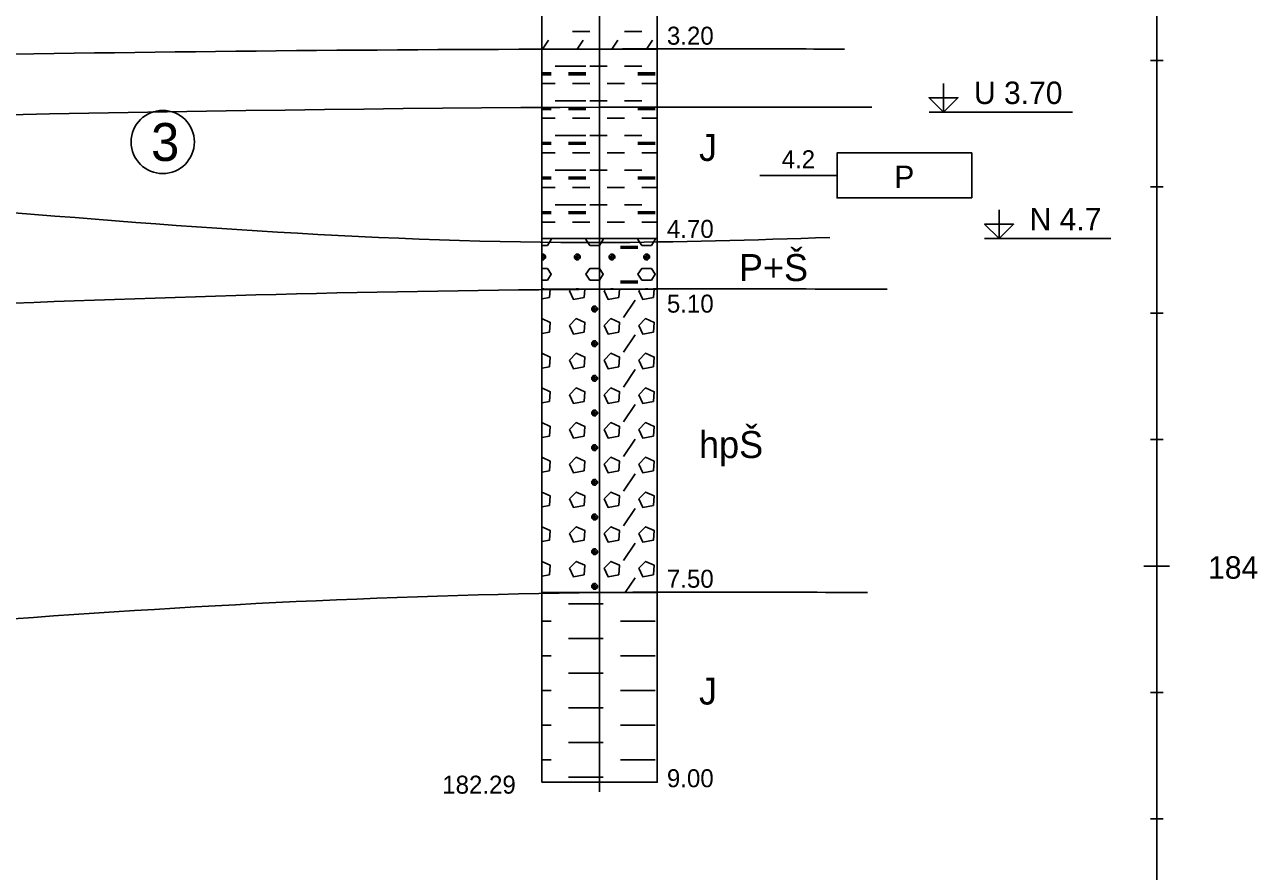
# Model space of a CAD drawing. Extents: x 3042 to 4120, y 576 to 2694.
# Drawn here: x 3483.02 to 3531.8, y 1564.76 to 1598.25 of the extents above; entities that cross this region are included whole.
import ezdxf

# ---------------------------------------------------------------- set-up
doc = ezdxf.new("R2010")
doc.units = 0
for name, color, linetype in [('17', 7, 'Continuous'), ('18', 7, 'Continuous'), ('19', 7, 'Continuous'), ('21', 7, 'Continuous'), ('51', 7, 'Continuous'), ('52', 7, 'Continuous'), ('53', 7, 'Continuous'), ('56', 7, 'Continuous'), ('61', 7, 'Continuous'), ('62', 7, 'Continuous'), ('HPV', 7, 'Continuous'), ('rozhraní', 7, 'Continuous')]:
    doc.layers.add(name, color=color, linetype=linetype)

msp = doc.modelspace()

# ---------------------------------------------------------------- linework, layer by layer
at = {"layer": '18'}
for p, q in [((3505.772, 1568.288), (3505.772, 1613.288)), ((3505.391, 1568.288), (3506.153, 1568.288)), ((3505.772, 1568.669), (3505.772, 1567.907))]:
    msp.add_line(p, q, dxfattribs=at)
at = {"layer": '19'}
for p, q in [((3527.568, 1596.838), (3528.076, 1596.838)), ((3527.568, 1591.838), (3528.076, 1591.838)), ((3527.568, 1586.838), (3528.076, 1586.838)), ((3527.568, 1581.838), (3528.076, 1581.838)), ((3527.314, 1576.838), (3528.33, 1576.838)), ((3527.568, 1571.838), (3528.076, 1571.838)), ((3527.568, 1566.838), (3528.076, 1566.838))]:
    msp.add_line(p, q, dxfattribs=at)
at = {"layer": '21'}
msp.add_line((3527.822, 1551.838), (3527.822, 1621.838), dxfattribs=at)
at = {"layer": '51'}
for p, q in [((3504.702, 1597.979), (3505.388, 1597.979)), ((3506.759, 1597.979), (3507.445, 1597.979)), ((3503.517, 1597.288), (3503.749, 1597.636)), ((3504.889, 1597.288), (3505.121, 1597.636)), ((3506.261, 1597.288), (3506.492, 1597.636)), ((3507.632, 1597.288), (3507.864, 1597.636)), ((3504.016, 1596.607), (3504.702, 1596.607)), ((3504.549, 1596.607), (3505.235, 1596.607)), ((3505.388, 1596.607), (3506.073, 1596.607)), ((3506.759, 1596.607), (3507.445, 1596.607)), ((3503.486, 1596.341), (3503.864, 1596.341)), ((3503.486, 1596.303), (3503.864, 1596.303)), ((3503.486, 1596.264), (3503.864, 1596.264)), ((3504.549, 1596.341), (3505.235, 1596.341)), ((3504.549, 1596.303), (3505.235, 1596.303)), ((3504.549, 1596.264), (3505.235, 1596.264)), ((3507.293, 1596.341), (3507.978, 1596.341)), ((3507.293, 1596.303), (3507.978, 1596.303)), ((3507.293, 1596.264), (3507.978, 1596.264)), ((3503.486, 1595.922), (3504.016, 1595.922)), ((3504.702, 1595.922), (3505.388, 1595.922)), ((3506.073, 1595.922), (3506.759, 1595.922)), ((3507.445, 1595.922), (3508.058, 1595.922)), ((3504.016, 1595.236), (3504.702, 1595.236)), ((3504.549, 1595.236), (3505.235, 1595.236)), ((3505.388, 1595.236), (3506.073, 1595.236)), ((3506.759, 1595.236), (3507.445, 1595.236)), ((3503.486, 1594.969), (3503.864, 1594.969)), ((3503.486, 1594.931), (3503.864, 1594.931)), ((3503.486, 1594.893), (3503.864, 1594.893)), ((3503.486, 1594.55), (3504.016, 1594.55)), ((3504.549, 1594.969), (3505.235, 1594.969)), ((3504.549, 1594.931), (3505.235, 1594.931)), ((3504.549, 1594.893), (3505.235, 1594.893)), ((3504.702, 1594.55), (3505.388, 1594.55)), ((3506.073, 1594.55), (3506.759, 1594.55)), ((3507.293, 1594.969), (3507.978, 1594.969)), ((3507.293, 1594.931), (3507.978, 1594.931)), ((3507.293, 1594.893), (3507.978, 1594.893)), ((3507.445, 1594.55), (3508.058, 1594.55)), ((3503.486, 1593.597), (3503.864, 1593.597)), ((3504.016, 1593.864), (3504.702, 1593.864)), ((3504.549, 1593.864), (3505.235, 1593.864)), ((3504.549, 1593.597), (3505.235, 1593.597)), ((3505.388, 1593.864), (3506.073, 1593.864)), ((3506.759, 1593.864), (3507.445, 1593.864)), ((3507.293, 1593.597), (3507.978, 1593.597)), ((3503.486, 1593.559), (3503.864, 1593.559)), ((3503.486, 1593.521), (3503.864, 1593.521)), ((3503.486, 1593.178), (3504.016, 1593.178)), ((3504.549, 1593.559), (3505.235, 1593.559)), ((3504.549, 1593.521), (3505.235, 1593.521)), ((3504.702, 1593.178), (3505.388, 1593.178)), ((3506.073, 1593.178), (3506.759, 1593.178)), ((3507.293, 1593.559), (3507.978, 1593.559)), ((3507.293, 1593.521), (3507.978, 1593.521)), ((3507.445, 1593.178), (3508.058, 1593.178)), ((3503.486, 1592.226), (3503.864, 1592.226)), ((3503.486, 1592.188), (3503.864, 1592.188)), ((3503.486, 1592.15), (3503.864, 1592.15)), ((3504.016, 1592.493), (3504.702, 1592.493)), ((3504.549, 1592.493), (3505.235, 1592.493)), ((3504.549, 1592.226), (3505.235, 1592.226)), ((3504.549, 1592.188), (3505.235, 1592.188)), ((3504.549, 1592.15), (3505.235, 1592.15)), ((3505.388, 1592.493), (3506.073, 1592.493)), ((3506.759, 1592.493), (3507.445, 1592.493)), ((3507.293, 1592.226), (3507.978, 1592.226)), ((3507.293, 1592.188), (3507.978, 1592.188)), ((3507.293, 1592.15), (3507.978, 1592.15)), ((3503.486, 1591.807), (3504.016, 1591.807)), ((3504.702, 1591.807), (3505.388, 1591.807)), ((3506.073, 1591.807), (3506.759, 1591.807)), ((3507.445, 1591.807), (3508.058, 1591.807)), ((3503.486, 1590.854), (3503.864, 1590.854)), ((3503.486, 1590.816), (3503.864, 1590.816)), ((3503.486, 1590.778), (3503.864, 1590.778)), ((3504.016, 1591.121), (3504.702, 1591.121)), ((3504.549, 1591.121), (3505.235, 1591.121)), ((3504.549, 1590.854), (3505.235, 1590.854)), ((3504.549, 1590.816), (3505.235, 1590.816)), ((3504.549, 1590.778), (3505.235, 1590.778)), ((3505.388, 1591.121), (3506.073, 1591.121)), ((3506.759, 1591.121), (3507.445, 1591.121)), ((3507.293, 1590.854), (3507.978, 1590.854)), ((3507.293, 1590.816), (3507.978, 1590.816)), ((3507.293, 1590.778), (3507.978, 1590.778)), ((3503.486, 1590.435), (3504.016, 1590.435)), ((3504.702, 1590.435), (3505.388, 1590.435)), ((3506.073, 1590.435), (3506.759, 1590.435)), ((3507.445, 1590.435), (3508.058, 1590.435)), ((3506.607, 1589.483), (3507.293, 1589.483)), ((3506.607, 1589.445), (3507.293, 1589.445)), ((3506.607, 1589.406), (3507.293, 1589.406)), ((3503.483, 1589.178), (3503.483, 1589.178)), ((3503.486, 1589.105), (3503.559, 1589.178)), ((3503.521, 1588.949), (3503.521, 1589.178)), ((3504.892, 1588.949), (3504.892, 1589.178)), ((3506.264, 1588.949), (3506.264, 1589.178)), ((3507.635, 1588.949), (3507.635, 1589.178)), ((3503.483, 1587.806), (3503.483, 1587.806)), ((3503.521, 1587.788), (3503.521, 1587.806)), ((3503.541, 1587.788), (3503.559, 1587.806)), ((3504.646, 1587.788), (3504.587, 1587.73)), ((3504.854, 1587.806), (3504.836, 1587.788)), ((3504.892, 1587.788), (3504.892, 1587.806)), ((3504.913, 1587.788), (3504.93, 1587.806)), ((3506.017, 1587.788), (3505.959, 1587.73)), ((3506.226, 1587.806), (3506.208, 1587.788)), ((3506.264, 1587.788), (3506.264, 1587.806)), ((3506.284, 1587.788), (3506.302, 1587.806)), ((3506.607, 1588.111), (3507.293, 1588.111)), ((3506.607, 1588.073), (3507.293, 1588.073)), ((3506.607, 1588.035), (3507.293, 1588.035)), ((3507.389, 1587.788), (3507.331, 1587.73)), ((3507.597, 1587.806), (3507.58, 1587.788)), ((3507.635, 1587.788), (3507.635, 1587.806)), ((3507.656, 1587.788), (3507.674, 1587.806)), ((3506.721, 1586.663), (3507.178, 1587.349)), ((3505.578, 1586.892), (3505.578, 1587.12)), ((3506.721, 1585.292), (3507.178, 1585.977)), ((3505.578, 1585.52), (3505.578, 1585.749)), ((3505.578, 1584.149), (3505.578, 1584.377)), ((3506.721, 1583.92), (3507.178, 1584.606)), ((3505.578, 1582.777), (3505.578, 1583.006)), ((3506.721, 1582.548), (3507.178, 1583.234)), ((3505.578, 1581.405), (3505.578, 1581.634)), ((3506.721, 1581.177), (3507.178, 1581.863)), ((3506.721, 1579.805), (3507.178, 1580.491)), ((3505.578, 1580.034), (3505.578, 1580.262)), ((3506.721, 1578.434), (3507.178, 1579.119)), ((3505.578, 1578.662), (3505.578, 1578.891)), ((3505.578, 1577.291), (3505.578, 1577.519)), ((3506.721, 1577.062), (3507.178, 1577.748)), ((3505.578, 1575.919), (3505.578, 1576.148)), ((3506.786, 1575.788), (3507.178, 1576.376)), ((3504.549, 1575.348), (3505.235, 1575.348)), ((3505.235, 1575.348), (3505.921, 1575.348)), ((3503.486, 1574.662), (3503.864, 1574.662)), ((3506.607, 1574.662), (3507.293, 1574.662)), ((3507.293, 1574.662), (3507.978, 1574.662)), ((3504.549, 1573.976), (3505.235, 1573.976)), ((3505.235, 1573.976), (3505.921, 1573.976)), ((3503.486, 1573.29), (3503.864, 1573.29)), ((3506.607, 1573.29), (3507.293, 1573.29)), ((3507.293, 1573.29), (3507.978, 1573.29)), ((3504.549, 1572.604), (3505.235, 1572.604)), ((3505.235, 1572.604), (3505.921, 1572.604)), ((3503.486, 1571.919), (3503.864, 1571.919)), ((3506.607, 1571.919), (3507.293, 1571.919)), ((3507.293, 1571.919), (3507.978, 1571.919)), ((3504.549, 1571.233), (3505.235, 1571.233)), ((3505.235, 1571.233), (3505.921, 1571.233)), ((3503.486, 1570.547), (3503.864, 1570.547)), ((3506.607, 1570.547), (3507.293, 1570.547)), ((3507.293, 1570.547), (3507.978, 1570.547)), ((3504.549, 1569.861), (3505.235, 1569.861)), ((3505.235, 1569.861), (3505.921, 1569.861)), ((3503.486, 1569.175), (3503.864, 1569.175)), ((3506.607, 1569.175), (3507.293, 1569.175)), ((3507.293, 1569.175), (3507.978, 1569.175)), ((3504.549, 1568.49), (3505.235, 1568.49)), ((3505.235, 1568.49), (3505.921, 1568.49))]:
    msp.add_line(p, q, dxfattribs=at)
for points in [[(3503.486, 1597.288), (3508.058, 1597.288), (3508.058, 1605.288), (3503.486, 1605.288)], [(3503.486, 1589.788), (3508.058, 1589.788), (3508.058, 1597.288), (3503.486, 1597.288)], [(3503.486, 1587.788), (3508.058, 1587.788), (3508.058, 1589.788), (3503.486, 1589.788)], [(3503.486, 1575.788), (3508.058, 1575.788), (3508.058, 1587.788), (3503.486, 1587.788)], [(3503.486, 1568.288), (3508.058, 1568.288), (3508.058, 1575.788), (3503.486, 1575.788)]]:
    msp.add_lwpolyline(points, close=True, dxfattribs=at)
for points in [[(3503.486, 1589.521), (3503.711, 1589.521), (3503.864, 1589.749), (3503.837, 1589.788)], [(3505.261, 1589.788), (3505.235, 1589.749), (3505.388, 1589.521)], [(3505.388, 1589.521), (3505.769, 1589.521), (3505.921, 1589.749), (3505.895, 1589.788)], [(3507.319, 1589.788), (3507.293, 1589.749), (3507.445, 1589.521)], [(3507.445, 1589.521), (3507.826, 1589.521), (3507.978, 1589.749), (3507.952, 1589.788)], [(3503.483, 1588.949), (3503.483, 1588.949), (3503.559, 1588.949), (3503.635, 1589.025), (3503.635, 1589.102), (3503.559, 1589.178), (3503.483, 1589.178), (3503.635, 1589.025), (3503.486, 1589.025)], [(3504.854, 1589.178), (3504.778, 1589.102), (3504.778, 1589.025), (3504.854, 1588.949), (3504.93, 1588.949), (3505.007, 1589.025), (3505.007, 1589.102), (3504.93, 1589.178), (3504.854, 1589.178), (3505.007, 1589.025), (3504.778, 1589.025), (3504.93, 1589.178)], [(3506.226, 1589.178), (3506.15, 1589.102), (3506.15, 1589.025), (3506.226, 1588.949), (3506.302, 1588.949), (3506.378, 1589.025), (3506.378, 1589.102), (3506.302, 1589.178), (3506.226, 1589.178), (3506.378, 1589.025), (3506.15, 1589.025), (3506.302, 1589.178)], [(3507.597, 1589.178), (3507.521, 1589.102), (3507.521, 1589.025), (3507.597, 1588.949), (3507.674, 1588.949), (3507.75, 1589.025), (3507.75, 1589.102), (3507.674, 1589.178), (3507.597, 1589.178), (3507.75, 1589.025), (3507.521, 1589.025), (3507.674, 1589.178)], [(3503.486, 1588.149), (3503.711, 1588.149), (3503.864, 1588.378), (3503.711, 1588.606), (3503.486, 1588.606)], [(3505.388, 1588.149), (3505.769, 1588.149), (3505.921, 1588.378), (3505.769, 1588.606), (3505.388, 1588.606), (3505.235, 1588.378), (3505.388, 1588.149)], [(3507.445, 1588.149), (3507.826, 1588.149), (3507.978, 1588.378), (3507.826, 1588.606), (3507.445, 1588.606), (3507.293, 1588.378), (3507.445, 1588.149)], [(3503.577, 1587.788), (3503.559, 1587.806), (3503.483, 1587.806), (3503.5, 1587.788)], [(3503.486, 1587.408), (3503.787, 1587.463), (3503.82, 1587.788)], [(3504.587, 1587.73), (3504.74, 1587.387), (3505.159, 1587.463), (3505.191, 1587.788)], [(3504.948, 1587.788), (3504.93, 1587.806), (3504.854, 1587.806), (3504.872, 1587.788)], [(3505.959, 1587.73), (3506.111, 1587.387), (3506.531, 1587.463), (3506.563, 1587.788)], [(3506.32, 1587.788), (3506.302, 1587.806), (3506.226, 1587.806), (3506.244, 1587.788)], [(3507.331, 1587.73), (3507.483, 1587.387), (3507.902, 1587.463), (3507.935, 1587.788)], [(3507.691, 1587.788), (3507.674, 1587.806), (3507.597, 1587.806), (3507.615, 1587.788)], [(3505.54, 1587.12), (3505.464, 1587.044), (3505.464, 1586.968), (3505.54, 1586.892), (3505.616, 1586.892), (3505.692, 1586.968), (3505.692, 1587.044), (3505.616, 1587.12), (3505.54, 1587.12), (3505.692, 1586.968), (3505.464, 1586.968), (3505.616, 1587.12)], [(3503.486, 1586.037), (3503.787, 1586.092), (3503.825, 1586.473), (3503.483, 1586.625), (3503.483, 1586.625)], [(3504.587, 1586.358), (3504.74, 1586.016), (3505.159, 1586.092), (3505.197, 1586.473), (3504.854, 1586.625), (3504.587, 1586.358)], [(3505.959, 1586.358), (3506.111, 1586.016), (3506.531, 1586.092), (3506.569, 1586.473), (3506.226, 1586.625), (3505.959, 1586.358)], [(3507.331, 1586.358), (3507.483, 1586.016), (3507.902, 1586.092), (3507.94, 1586.473), (3507.597, 1586.625), (3507.331, 1586.358)], [(3505.54, 1585.749), (3505.464, 1585.673), (3505.464, 1585.596), (3505.54, 1585.52), (3505.616, 1585.52), (3505.692, 1585.596), (3505.692, 1585.673), (3505.616, 1585.749), (3505.54, 1585.749), (3505.692, 1585.596), (3505.464, 1585.596), (3505.616, 1585.749)], [(3503.486, 1584.665), (3503.787, 1584.72), (3503.825, 1585.101), (3503.483, 1585.254), (3503.483, 1585.254)], [(3504.587, 1584.987), (3504.74, 1584.644), (3505.159, 1584.72), (3505.197, 1585.101), (3504.854, 1585.254), (3504.587, 1584.987)], [(3505.959, 1584.987), (3506.111, 1584.644), (3506.531, 1584.72), (3506.569, 1585.101), (3506.226, 1585.254), (3505.959, 1584.987)], [(3507.331, 1584.987), (3507.483, 1584.644), (3507.902, 1584.72), (3507.94, 1585.101), (3507.597, 1585.254), (3507.331, 1584.987)], [(3505.54, 1584.377), (3505.464, 1584.301), (3505.464, 1584.225), (3505.54, 1584.149), (3505.616, 1584.149), (3505.692, 1584.225), (3505.692, 1584.301), (3505.616, 1584.377), (3505.54, 1584.377), (3505.692, 1584.225), (3505.464, 1584.225), (3505.616, 1584.377)], [(3503.486, 1583.294), (3503.787, 1583.349), (3503.825, 1583.73), (3503.483, 1583.882), (3503.483, 1583.882)], [(3504.587, 1583.615), (3504.74, 1583.272), (3505.159, 1583.349), (3505.197, 1583.73), (3504.854, 1583.882), (3504.587, 1583.615)], [(3505.959, 1583.615), (3506.111, 1583.272), (3506.531, 1583.349), (3506.569, 1583.73), (3506.226, 1583.882), (3505.959, 1583.615)], [(3507.331, 1583.615), (3507.483, 1583.272), (3507.902, 1583.349), (3507.94, 1583.73), (3507.597, 1583.882), (3507.331, 1583.615)], [(3505.54, 1583.006), (3505.464, 1582.929), (3505.464, 1582.853), (3505.54, 1582.777), (3505.616, 1582.777), (3505.692, 1582.853), (3505.692, 1582.929), (3505.616, 1583.006), (3505.54, 1583.006), (3505.692, 1582.853), (3505.464, 1582.853), (3505.616, 1583.006)], [(3503.486, 1581.922), (3503.787, 1581.977), (3503.825, 1582.358), (3503.483, 1582.51), (3503.483, 1582.51)], [(3504.587, 1582.244), (3504.74, 1581.901), (3505.159, 1581.977), (3505.197, 1582.358), (3504.854, 1582.51), (3504.587, 1582.244)], [(3505.959, 1582.244), (3506.111, 1581.901), (3506.531, 1581.977), (3506.569, 1582.358), (3506.226, 1582.51), (3505.959, 1582.244)], [(3507.331, 1582.244), (3507.483, 1581.901), (3507.902, 1581.977), (3507.94, 1582.358), (3507.597, 1582.51), (3507.331, 1582.244)], [(3505.54, 1581.634), (3505.464, 1581.558), (3505.464, 1581.482), (3505.54, 1581.405), (3505.616, 1581.405), (3505.692, 1581.482), (3505.692, 1581.558), (3505.616, 1581.634), (3505.54, 1581.634), (3505.692, 1581.482), (3505.464, 1581.482), (3505.616, 1581.634)], [(3503.486, 1580.55), (3503.787, 1580.605), (3503.825, 1580.986), (3503.483, 1581.139), (3503.483, 1581.139)], [(3504.587, 1580.872), (3504.74, 1580.529), (3505.159, 1580.605), (3505.197, 1580.986), (3504.854, 1581.139), (3504.587, 1580.872)], [(3505.959, 1580.872), (3506.111, 1580.529), (3506.531, 1580.605), (3506.569, 1580.986), (3506.226, 1581.139), (3505.959, 1580.872)], [(3507.331, 1580.872), (3507.483, 1580.529), (3507.902, 1580.605), (3507.94, 1580.986), (3507.597, 1581.139), (3507.331, 1580.872)], [(3505.54, 1580.262), (3505.464, 1580.186), (3505.464, 1580.11), (3505.54, 1580.034), (3505.616, 1580.034), (3505.692, 1580.11), (3505.692, 1580.186), (3505.616, 1580.262), (3505.54, 1580.262), (3505.692, 1580.11), (3505.464, 1580.11), (3505.616, 1580.262)], [(3503.486, 1579.179), (3503.787, 1579.234), (3503.825, 1579.615), (3503.483, 1579.767), (3503.483, 1579.767)], [(3504.587, 1579.5), (3504.74, 1579.158), (3505.159, 1579.234), (3505.197, 1579.615), (3504.854, 1579.767), (3504.587, 1579.5)], [(3505.959, 1579.5), (3506.111, 1579.158), (3506.531, 1579.234), (3506.569, 1579.615), (3506.226, 1579.767), (3505.959, 1579.5)], [(3507.331, 1579.5), (3507.483, 1579.158), (3507.902, 1579.234), (3507.94, 1579.615), (3507.597, 1579.767), (3507.331, 1579.5)], [(3505.54, 1578.891), (3505.464, 1578.815), (3505.464, 1578.738), (3505.54, 1578.662), (3505.616, 1578.662), (3505.692, 1578.738), (3505.692, 1578.815), (3505.616, 1578.891), (3505.54, 1578.891), (3505.692, 1578.738), (3505.464, 1578.738), (3505.616, 1578.891)], [(3503.486, 1577.807), (3503.787, 1577.862), (3503.825, 1578.243), (3503.483, 1578.396), (3503.483, 1578.396)], [(3504.587, 1578.129), (3504.74, 1577.786), (3505.159, 1577.862), (3505.197, 1578.243), (3504.854, 1578.396), (3504.587, 1578.129)], [(3505.959, 1578.129), (3506.111, 1577.786), (3506.531, 1577.862), (3506.569, 1578.243), (3506.226, 1578.396), (3505.959, 1578.129)], [(3507.331, 1578.129), (3507.483, 1577.786), (3507.902, 1577.862), (3507.94, 1578.243), (3507.597, 1578.396), (3507.331, 1578.129)], [(3505.54, 1577.519), (3505.464, 1577.443), (3505.464, 1577.367), (3505.54, 1577.291), (3505.616, 1577.291), (3505.692, 1577.367), (3505.692, 1577.443), (3505.616, 1577.519), (3505.54, 1577.519), (3505.692, 1577.367), (3505.464, 1577.367), (3505.616, 1577.519)], [(3503.486, 1576.436), (3503.787, 1576.491), (3503.825, 1576.872), (3503.483, 1577.024), (3503.483, 1577.024)], [(3504.587, 1576.757), (3504.74, 1576.414), (3505.159, 1576.491), (3505.197, 1576.872), (3504.854, 1577.024), (3504.587, 1576.757)], [(3505.959, 1576.757), (3506.111, 1576.414), (3506.531, 1576.491), (3506.569, 1576.872), (3506.226, 1577.024), (3505.959, 1576.757)], [(3507.331, 1576.757), (3507.483, 1576.414), (3507.902, 1576.491), (3507.94, 1576.872), (3507.597, 1577.024), (3507.331, 1576.757)], [(3505.54, 1576.148), (3505.464, 1576.071), (3505.464, 1575.995), (3505.54, 1575.919), (3505.616, 1575.919), (3505.692, 1575.995), (3505.692, 1576.071), (3505.616, 1576.148), (3505.54, 1576.148), (3505.692, 1575.995), (3505.464, 1575.995), (3505.616, 1576.148)]]:
    msp.add_lwpolyline(points, dxfattribs=at)
at = {"layer": '53'}
for p, q in [((3503.486, 1613.288), (3503.486, 1568.288)), ((3508.058, 1613.288), (3508.058, 1568.288)), ((3503.486, 1597.288), (3508.058, 1597.288)), ((3503.486, 1589.788), (3508.058, 1589.788)), ((3503.486, 1587.788), (3508.058, 1587.788)), ((3503.486, 1575.788), (3508.058, 1575.788)), ((3503.486, 1568.288), (3508.058, 1568.288))]:
    msp.add_line(p, q, dxfattribs=at)
at = {"layer": '56'}
for p, q in [((3505.772, 1597.669), (3505.772, 1596.907)), ((3505.391, 1597.288), (3506.153, 1597.288)), ((3505.772, 1590.169), (3505.772, 1589.407)), ((3505.391, 1589.788), (3506.153, 1589.788)), ((3505.391, 1587.788), (3506.153, 1587.788)), ((3505.772, 1588.169), (3505.772, 1587.407)), ((3505.772, 1576.169), (3505.772, 1575.407)), ((3505.391, 1575.788), (3506.153, 1575.788)), ((3505.391, 1568.288), (3506.153, 1568.288)), ((3505.772, 1568.669), (3505.772, 1567.907))]:
    msp.add_line(p, q, dxfattribs=at)
at = {"layer": '61'}
for p, q in [((3518.811, 1594.788), (3524.484, 1594.788)), ((3521.012, 1589.788), (3526.007, 1589.788))]:
    msp.add_line(p, q, dxfattribs=at)
for points in [[(3519.383, 1595.931), (3519.383, 1594.788), (3518.811, 1595.36), (3519.954, 1595.36), (3519.383, 1594.788)], [(3521.583, 1590.931), (3521.583, 1589.788), (3521.012, 1590.36), (3522.155, 1590.36), (3521.583, 1589.788)]]:
    msp.add_lwpolyline(points, dxfattribs=at)
at = {"layer": '62'}
msp.add_line((3512.122, 1592.288), (3515.17, 1592.288), dxfattribs=at)
msp.add_lwpolyline([(3520.504, 1591.399), (3515.17, 1591.399), (3515.17, 1593.177), (3520.504, 1593.177), (3520.504, 1591.399)], dxfattribs=at)
at = {"layer": 'HPV'}
msp.add_spline([(3258.558, 1595.438), (3265.132, 1595.438), (3304.222, 1591.874), (3343.272, 1592.467), (3406.282, 1592.961), (3505.772, 1594.985), (3516.554, 1594.985)], degree=3, dxfattribs=at)
at = {"layer": 'rozhraní'}
msp.add_circle((3488.489, 1593.611), 1.25, dxfattribs=at)
for points in [[(3343.149, 1592.908), (3343.272, 1592.888), (3351.552, 1592.438), (3359.888, 1593.128), (3368.248, 1594.122), (3372.427, 1594.472), (3376.599, 1594.586), (3384.02, 1594.321), (3391.441, 1593.85), (3398.862, 1593.447), (3406.282, 1593.388), (3418.367, 1594.021), (3430.442, 1595.004), (3442.519, 1595.967), (3454.612, 1596.538), (3467.4, 1596.805), (3480.19, 1597.046), (3505.772, 1597.288), (3515.471, 1597.288)], [(3514.887, 1589.833), (3505.845, 1589.635), (3454.612, 1592.538), (3406.282, 1588.388), (3376.599, 1586.586), (3364.06, 1589.145), (3356.751, 1592.851)], [(3388.049, 1585.144), (3406.282, 1583.388), (3454.612, 1585.538), (3505.772, 1587.788), (3517.156, 1587.788)], [(3259.44, 1578.878), (3265.132, 1578.438), (3304.222, 1572.038), (3343.272, 1565.888), (3376.602, 1571.588), (3406.282, 1569.388), (3454.612, 1572.038), (3505.772, 1575.788), (3516.375, 1575.788)]]:
    msp.add_spline(points, degree=3, dxfattribs=at)

# ---------------------------------------------------------------- texts
at = {"layer": '17'}
msp.add_text('182.29', height=0.7112, dxfattribs=at).set_placement((3499.549, 1567.836))
at = {"layer": '19'}
msp.add_text('184', height=0.889, dxfattribs=at).set_placement((3529.854, 1576.337))
at = {"layer": '52'}
for s, height, p in [('3.20', 0.7112, (3508.439, 1597.46)), ('J', 1.067, (3509.709, 1592.86)), ('4.70', 0.7112, (3508.439, 1589.819)), ('P+Š', 1.0668, (3511.288, 1588.11)), ('5.10', 0.7112, (3508.439, 1586.862)), ('hpŠ', 1.0668, (3509.709, 1581.11)), ('7.50', 0.7112, (3508.439, 1575.98)), ('J', 1.067, (3509.709, 1571.36)), ('9.00', 0.7112, (3508.439, 1568.09))]:
    msp.add_text(s, height=height, dxfattribs=at).set_placement(p)
at = {"layer": '61'}
for s, p in [('U 3.70', (3520.589, 1595.112)), ('N 4.7', (3522.79, 1590.112))]:
    msp.add_text(s, height=0.889, dxfattribs=at).set_placement(p)
at = {"layer": '62'}
for s, height, p in [('4.2', 0.7112, (3512.979, 1592.573)), ('P', 0.889, (3517.435, 1591.787))]:
    msp.add_text(s, height=height, dxfattribs=at).set_placement(p)
at = {"layer": 'rozhraní'}
msp.add_text('3', height=1.5, dxfattribs=at).set_placement((3488.028, 1592.861))

doc.saveas('drawing.dxf')
